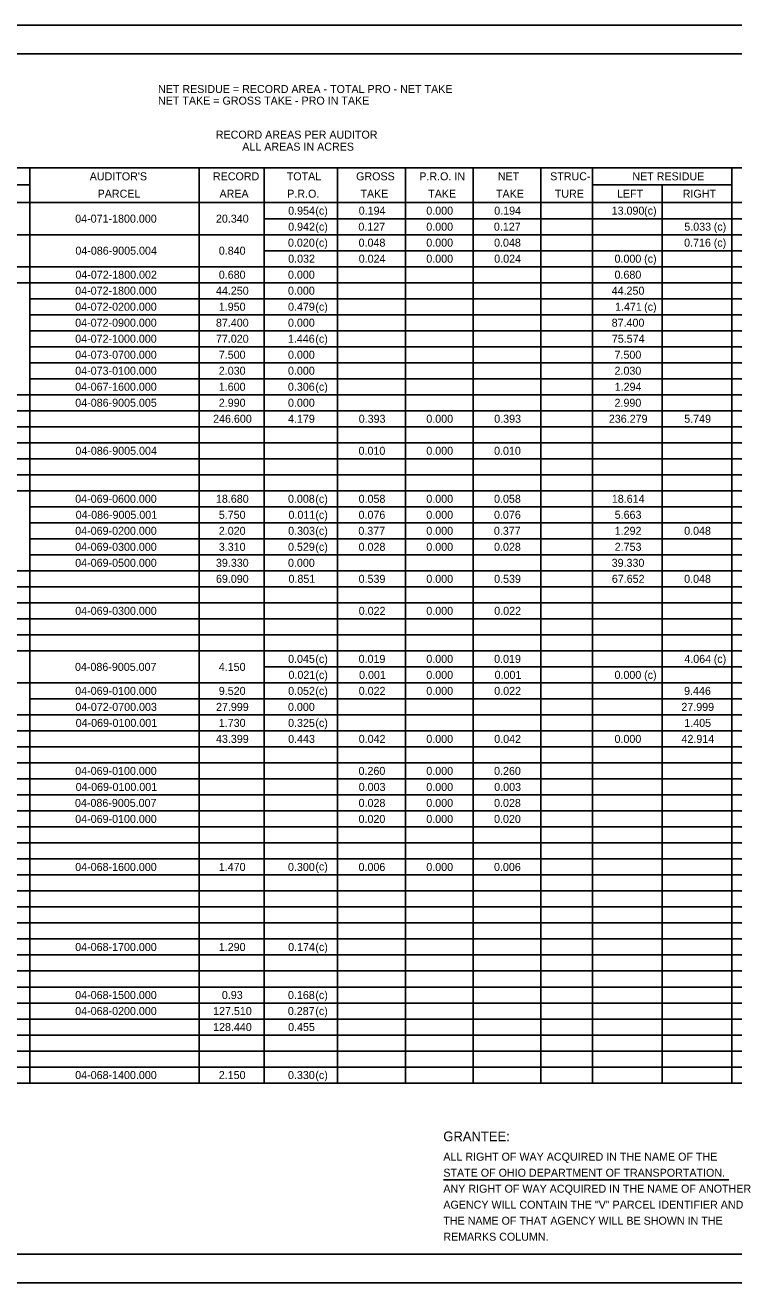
# Model space of a CAD drawing. Extents: x 0 to 34, y 0 to 22.
# Drawn here: x 11.96 to 24.36, y 0 to 22 of the extents above; entities that cross this region are included whole.
import ezdxf

# ---------------------------------------------------------------- set-up
doc = ezdxf.new("R2010")
doc.units = 0
for name, color, linetype in [('RW_P_Text', 7, 'Continuous'), ('SH_Border', 7, 'Continuous'), ('SH_Cut_Line', 7, 'Continuous'), ('SH_Text', 7, 'Continuous')]:
    doc.layers.add(name, color=color, linetype=linetype)

msp = doc.modelspace()

# ---------------------------------------------------------------- linework, layer by layer
at = {"layer": 'SH_Border'}
msp.add_lwpolyline([(1.5, 21.5), (33.5, 21.5), (33.5, 0.5), (1.5, 0.5)], close=True, dxfattribs=at)
at = {"layer": 'SH_Cut_Line'}
msp.add_lwpolyline([(0, 0), (34, 0), (34, 22), (0, 22)], close=True, dxfattribs=at)
at = {"layer": 'SH_Text'}
for p, q in [((1.5, 19.505), (32.02, 19.505)), ((12.041, 19.505), (12.041, 3.495)), ((15.006, 19.505), (15.006, 3.495)), ((16.142, 19.505), (16.142, 3.495)), ((17.427, 19.505), (17.427, 7.135)), ((18.613, 19.505), (18.613, 3.495)), ((19.799, 19.505), (19.799, 3.495)), ((20.985, 19.505), (20.985, 3.495)), ((21.891, 19.505), (21.891, 3.495)), ((24.328, 19.505), (24.328, 3.495)), ((9.604, 19.208), (12.041, 19.208)), ((21.891, 19.208), (24.328, 19.208)), ((23.109, 19.208), (23.109, 3.495)), ((1.5, 18.895), (32.02, 18.895)), ((16.142, 18.615), (32.02, 18.615)), ((1.5, 18.335), (32.02, 18.335)), ((16.142, 18.055), (32.02, 18.055)), ((1.5, 17.775), (32.02, 17.775)), ((1.5, 17.495), (32.02, 17.495)), ((12.041, 17.215), (32.02, 17.215)), ((12.041, 16.935), (32.02, 16.935)), ((12.041, 16.655), (32.02, 16.655)), ((12.041, 16.375), (32.02, 16.375)), ((12.041, 16.095), (32.02, 16.095)), ((12.041, 15.815), (32.02, 15.815)), ((1.5, 15.535), (32.02, 15.535)), ((1.5, 15.255), (32.02, 15.255)), ((1.5, 14.975), (32.02, 14.975)), ((1.5, 14.695), (32.02, 14.695)), ((1.5, 14.415), (32.02, 14.415)), ((1.5, 14.135), (32.02, 14.135)), ((1.5, 13.855), (32.02, 13.855)), ((12.041, 13.575), (32.02, 13.575)), ((12.041, 13.295), (32.02, 13.295)), ((12.041, 13.015), (32.02, 13.015)), ((12.041, 12.735), (32.02, 12.735)), ((1.5, 12.455), (32.02, 12.455)), ((1.5, 12.175), (32.02, 12.175)), ((1.5, 11.895), (32.02, 11.895)), ((1.5, 11.615), (32.02, 11.615)), ((1.5, 11.335), (32.02, 11.335)), ((1.5, 11.055), (32.02, 11.055)), ((16.142, 10.775), (32.02, 10.775)), ((1.5, 10.495), (32.02, 10.495)), ((12.041, 10.215), (32.02, 10.215)), ((1.5, 9.935), (32.02, 9.935)), ((1.5, 9.655), (32.02, 9.655)), ((1.5, 9.375), (32.02, 9.375)), ((1.5, 9.095), (32.02, 9.095)), ((9.604, 8.815), (32.02, 8.815)), ((1.5, 8.535), (32.02, 8.535)), ((1.5, 8.255), (32.02, 8.255)), ((1.5, 7.975), (32.02, 7.975)), ((1.5, 7.695), (32.02, 7.695)), ((1.5, 7.415), (32.02, 7.415)), ((1.5, 7.135), (32.02, 7.135)), ((17.427, 7.135), (17.427, 6.855)), ((17.427, 7.135), (17.427, 6.855)), ((1.5, 6.855), (32.02, 6.855)), ((17.427, 6.855), (17.427, 3.495)), ((1.5, 6.575), (32.02, 6.575)), ((1.5, 6.295), (32.02, 6.295)), ((1.5, 6.015), (32.02, 6.015)), ((1.5, 5.735), (32.02, 5.735)), ((1.5, 5.455), (32.02, 5.455)), ((1.5, 5.175), (32.02, 5.175)), ((9.604, 4.895), (32.02, 4.895)), ((1.5, 4.615), (32.02, 4.615)), ((1.5, 4.335), (32.02, 4.335)), ((1.5, 4.055), (32.02, 4.055)), ((1.5, 3.775), (32.02, 3.775)), ((1.5, 3.495), (32.02, 3.495)), ((19.278, 1.8), (24.273, 1.8))]:
    msp.add_line(p, q, dxfattribs=at)

# ---------------------------------------------------------------- texts
at = {"layer": 'RW_P_Text'}
for p in [(17.038, 18.685), (22.792, 18.685), (17.038, 18.405), (24.011, 18.405), (17.038, 18.125), (24.011, 18.125), (22.792, 17.845), (17.038, 17.005), (22.792, 17.005), (17.038, 16.445), (17.038, 15.605), (17.038, 13.645), (17.038, 13.365), (17.038, 13.085), (17.038, 12.805), (17.038, 10.845), (24.011, 10.845), (17.038, 10.565), (22.792, 10.565), (17.038, 10.285), (17.038, 9.725), (17.038, 7.214), (17.038, 5.805), (17.038, 4.965), (17.038, 4.685), (17.038, 3.565)]:
    msp.add_text('(c)', height=0.14, dxfattribs=at).set_placement(p)
at = {"layer": 'SH_Text'}
for s, height, p in [('NET RESIDUE = RECORD AREA - TOTAL PRO - NET TAKE', 0.14, (14.284, 20.813)), ('NET TAKE = GROSS TAKE - PRO IN TAKE', 0.14, (14.284, 20.61)), ('RECORD AREAS PER AUDITOR', 0.14, (15.296, 20.015)), ('ALL AREAS IN ACRES', 0.14, (15.758, 19.805)), ("AUDITOR'S", 0.14, (13.089, 19.286)), ('RECORD', 0.14, (15.245, 19.286)), ('TOTAL', 0.14, (16.537, 19.286)), ('GROSS', 0.14, (17.751, 19.286)), ('P.R.O. IN', 0.14, (18.857, 19.286)), ('NET', 0.14, (20.232, 19.286)), ('STRUC-', 0.14, (21.147, 19.286)), ('NET RESIDUE', 0.14, (22.586, 19.286)), ('PARCEL', 0.14, (13.227, 18.982)), ('AREA', 0.14, (15.36, 18.982)), ('P.R.O.', 0.14, (16.546, 18.982)), ('TAKE', 0.14, (17.827, 18.982)), ('TAKE', 0.14, (19.013, 18.982)), ('TAKE', 0.14, (20.199, 18.982)), ('TURE', 0.14, (21.228, 18.982)), ('LEFT', 0.14, (22.317, 18.982)), ('RIGHT', 0.14, (23.468, 18.982)), ('0.954', 0.14, (16.562, 18.685)), ('0.194', 0.14, (17.797, 18.685)), ('0.000', 0.14, (18.98, 18.685)), ('0.194', 0.14, (20.169, 18.685)), ('13.090', 0.14, (22.224, 18.685)), ('04-071-1800.000', 0.14, (12.835, 18.545)), ('20.340', 0.14, (15.298, 18.545)), ('0.942', 0.14, (16.562, 18.405)), ('0.127', 0.14, (17.791, 18.405)), ('0.000', 0.14, (18.98, 18.405)), ('0.127', 0.14, (20.163, 18.405)), ('5.033', 0.14, (23.496, 18.405)), ('0.020', 0.14, (16.559, 18.125)), ('0.048', 0.14, (17.795, 18.125)), ('0.000', 0.14, (18.98, 18.125)), ('0.048', 0.14, (20.166, 18.125)), ('0.716', 0.14, (23.492, 18.125)), ('04-086-9005.004', 0.14, (12.838, 17.985)), ('0.840', 0.14, (15.348, 17.985)), ('0.032', 0.14, (16.562, 17.845)), ('0.024', 0.14, (17.797, 17.845)), ('0.000', 0.14, (18.98, 17.845)), ('0.024', 0.14, (20.169, 17.845)), ('0.000', 0.14, (22.274, 17.845)), ('04-072-1800.002', 0.14, (12.838, 17.565)), ('0.680', 0.14, (15.348, 17.565)), ('0.000', 0.14, (16.559, 17.565)), ('0.680', 0.14, (22.274, 17.565)), ('04-072-1800.000', 0.14, (12.835, 17.285)), ('44.250', 0.14, (15.298, 17.285)), ('0.000', 0.14, (16.559, 17.285)), ('44.250', 0.14, (22.224, 17.285)), ('04-072-0200.000', 0.14, (12.835, 17.005)), ('1.950', 0.14, (15.348, 17.005)), ('0.479', 0.14, (16.56, 17.005)), ('1.471', 0.14, (22.283, 17.005)), ('04-072-0900.000', 0.14, (12.835, 16.725)), ('87.400', 0.14, (15.298, 16.725)), ('0.000', 0.14, (16.559, 16.725)), ('87.400', 0.14, (22.224, 16.725)), ('04-072-1000.000', 0.14, (12.835, 16.445)), ('77.020', 0.14, (15.298, 16.445)), ('1.446', 0.14, (16.558, 16.445)), ('75.574', 0.14, (22.227, 16.445)), ('04-073-0700.000', 0.14, (12.835, 16.165)), ('7.500', 0.14, (15.348, 16.165)), ('0.000', 0.14, (16.559, 16.165)), ('7.500', 0.14, (22.274, 16.165)), ('04-073-0100.000', 0.14, (12.835, 15.885)), ('2.030', 0.14, (15.348, 15.885)), ('0.000', 0.14, (16.559, 15.885)), ('2.030', 0.14, (22.274, 15.885)), ('04-067-1600.000', 0.14, (12.835, 15.605)), ('1.600', 0.14, (15.348, 15.605)), ('0.306', 0.14, (16.558, 15.605)), ('1.294', 0.14, (22.277, 15.605)), ('04-086-9005.005', 0.14, (12.836, 15.325)), ('2.990', 0.14, (15.348, 15.325)), ('0.000', 0.14, (16.559, 15.325)), ('2.990', 0.14, (22.274, 15.325)), ('246.600', 0.14, (15.248, 15.045)), ('4.179', 0.14, (16.56, 15.045)), ('0.393', 0.14, (17.797, 15.045)), ('0.000', 0.14, (18.98, 15.045)), ('0.393', 0.14, (20.169, 15.045)), ('236.279', 0.14, (22.175, 15.045)), ('5.749', 0.14, (23.494, 15.045)), ('04-086-9005.004', 0.14, (12.838, 14.485)), ('0.010', 0.14, (17.794, 14.485)), ('0.000', 0.14, (18.98, 14.485)), ('0.010', 0.14, (20.166, 14.485)), ('04-069-0600.000', 0.14, (12.835, 13.645)), ('18.680', 0.14, (15.298, 13.645)), ('0.008', 0.14, (16.559, 13.645)), ('0.058', 0.14, (17.795, 13.645)), ('0.000', 0.14, (18.98, 13.645)), ('0.058', 0.14, (20.166, 13.645)), ('18.614', 0.14, (22.227, 13.645)), ('04-086-9005.001', 0.14, (12.843, 13.365)), ('5.750', 0.14, (15.348, 13.365)), ('0.011', 0.14, (16.568, 13.365)), ('0.076', 0.14, (17.794, 13.365)), ('0.000', 0.14, (18.98, 13.365)), ('0.076', 0.14, (20.165, 13.365)), ('5.663', 0.14, (22.277, 13.365)), ('04-069-0200.000', 0.14, (12.835, 13.085)), ('2.020', 0.14, (15.348, 13.085)), ('0.303', 0.14, (16.562, 13.085)), ('0.377', 0.14, (17.791, 13.085)), ('0.000', 0.14, (18.98, 13.085)), ('0.377', 0.14, (20.163, 13.085)), ('1.292', 0.14, (22.277, 13.085)), ('0.048', 0.14, (23.493, 13.085)), ('04-069-0300.000', 0.14, (12.835, 12.805)), ('3.310', 0.14, (15.348, 12.805)), ('0.529', 0.14, (16.56, 12.805)), ('0.028', 0.14, (17.795, 12.805)), ('0.000', 0.14, (18.98, 12.805)), ('0.028', 0.14, (20.166, 12.805)), ('2.753', 0.14, (22.277, 12.805)), ('04-069-0500.000', 0.14, (12.835, 12.525)), ('39.330', 0.14, (15.298, 12.525)), ('0.000', 0.14, (16.559, 12.525)), ('39.330', 0.14, (22.224, 12.525)), ('69.090', 0.14, (15.298, 12.245)), ('0.851', 0.14, (16.568, 12.245)), ('0.539', 0.14, (17.795, 12.245)), ('0.000', 0.14, (18.98, 12.245)), ('0.539', 0.14, (20.167, 12.245)), ('67.652', 0.14, (22.227, 12.245)), ('0.048', 0.14, (23.493, 12.245)), ('04-069-0300.000', 0.14, (12.835, 11.685)), ('0.022', 0.14, (17.797, 11.685)), ('0.000', 0.14, (18.98, 11.685)), ('0.022', 0.14, (20.169, 11.685)), ('04-086-9005.007', 0.14, (12.831, 10.705)), ('4.150', 0.14, (15.348, 10.705)), ('0.045', 0.14, (16.561, 10.845)), ('0.019', 0.14, (17.795, 10.845)), ('0.000', 0.14, (18.98, 10.845)), ('0.019', 0.14, (20.167, 10.845)), ('4.064', 0.14, (23.496, 10.845)), ('0.021', 0.14, (16.568, 10.565)), ('0.001', 0.14, (17.803, 10.565)), ('0.000', 0.14, (18.98, 10.565)), ('0.001', 0.14, (20.175, 10.565)), ('0.000', 0.14, (22.274, 10.565)), ('04-069-0100.000', 0.14, (12.835, 10.285)), ('9.520', 0.14, (15.348, 10.285)), ('0.052', 0.14, (16.562, 10.285)), ('0.022', 0.14, (17.797, 10.285)), ('0.000', 0.14, (18.98, 10.285)), ('0.022', 0.14, (20.169, 10.285)), ('9.446', 0.14, (23.492, 10.285)), ('04-072-0700.003', 0.14, (12.838, 10.005)), ('27.999', 0.14, (15.299, 10.005)), ('0.000', 0.14, (16.559, 10.005)), ('27.999', 0.14, (23.444, 10.005)), ('04-069-0100.001', 0.14, (12.843, 9.725)), ('1.730', 0.14, (15.348, 9.725)), ('0.325', 0.14, (16.561, 9.725)), ('1.405', 0.14, (23.495, 9.725)), ('43.399', 0.14, (15.299, 9.445)), ('0.443', 0.14, (16.562, 9.445)), ('0.042', 0.14, (17.797, 9.445)), ('0.000', 0.14, (18.98, 9.445)), ('0.042', 0.14, (20.169, 9.445)), ('0.000', 0.14, (22.274, 9.445)), ('42.914', 0.14, (23.446, 9.445)), ('04-069-0100.000', 0.14, (12.835, 8.885)), ('0.260', 0.14, (17.794, 8.885)), ('0.000', 0.14, (18.98, 8.885)), ('0.260', 0.14, (20.166, 8.885)), ('04-069-0100.001', 0.14, (12.843, 8.605)), ('0.003', 0.14, (17.797, 8.605)), ('0.000', 0.14, (18.98, 8.605)), ('0.003', 0.14, (20.169, 8.605)), ('04-086-9005.007', 0.14, (12.831, 8.325)), ('0.028', 0.14, (17.795, 8.325)), ('0.000', 0.14, (18.98, 8.325)), ('0.028', 0.14, (20.166, 8.325)), ('04-069-0100.000', 0.14, (12.835, 8.045)), ('0.020', 0.14, (17.794, 8.045)), ('0.000', 0.14, (18.98, 8.045)), ('0.020', 0.14, (20.166, 8.045)), ('04-068-1600.000', 0.14, (12.835, 7.205)), ('1.470', 0.14, (15.348, 7.205)), ('0.300', 0.14, (16.559, 7.205)), ('0.006', 0.14, (17.794, 7.205)), ('0.000', 0.14, (18.98, 7.205)), ('0.006', 0.14, (20.165, 7.205)), ('04-068-1700.000', 0.14, (12.835, 5.805)), ('1.290', 0.14, (15.348, 5.805)), ('0.174', 0.14, (16.562, 5.805)), ('04-068-1500.000', 0.14, (12.835, 4.965)), ('0.93', 0.14, (15.402, 4.965)), ('0.168', 0.14, (16.559, 4.965)), ('04-068-0200.000', 0.14, (12.835, 4.685)), ('127.510', 0.14, (15.248, 4.685)), ('0.287', 0.14, (16.556, 4.685)), ('128.440', 0.14, (15.248, 4.405)), ('0.455', 0.14, (16.561, 4.405)), ('04-068-1400.000', 0.14, (12.835, 3.565)), ('2.150', 0.14, (15.348, 3.565)), ('0.330', 0.14, (16.559, 3.565)), ('GRANTEE:', 0.17, (19.278, 2.477)), ('ALL RIGHT OF WAY ACQUIRED IN THE NAME OF THE', 0.14, (19.278, 2.137)), ('STATE OF OHIO DEPARTMENT OF TRANSPORTATION.', 0.14, (19.278, 1.857)), ('ANY RIGHT OF WAY ACQUIRED IN THE NAME OF ANOTHER ', 0.14, (19.278, 1.577)), ('AGENCY WILL CONTAIN THE "V" PARCEL IDENTIFIER AND ', 0.14, (19.278, 1.297)), ('THE NAME OF THAT AGENCY WILL BE SHOWN IN THE ', 0.14, (19.278, 1.017)), ('REMARKS COLUMN.', 0.14, (19.278, 0.737))]:
    msp.add_text(s, height=height, dxfattribs=at).set_placement(p)

doc.saveas('drawing.dxf')
